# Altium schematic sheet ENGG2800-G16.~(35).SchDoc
size A3
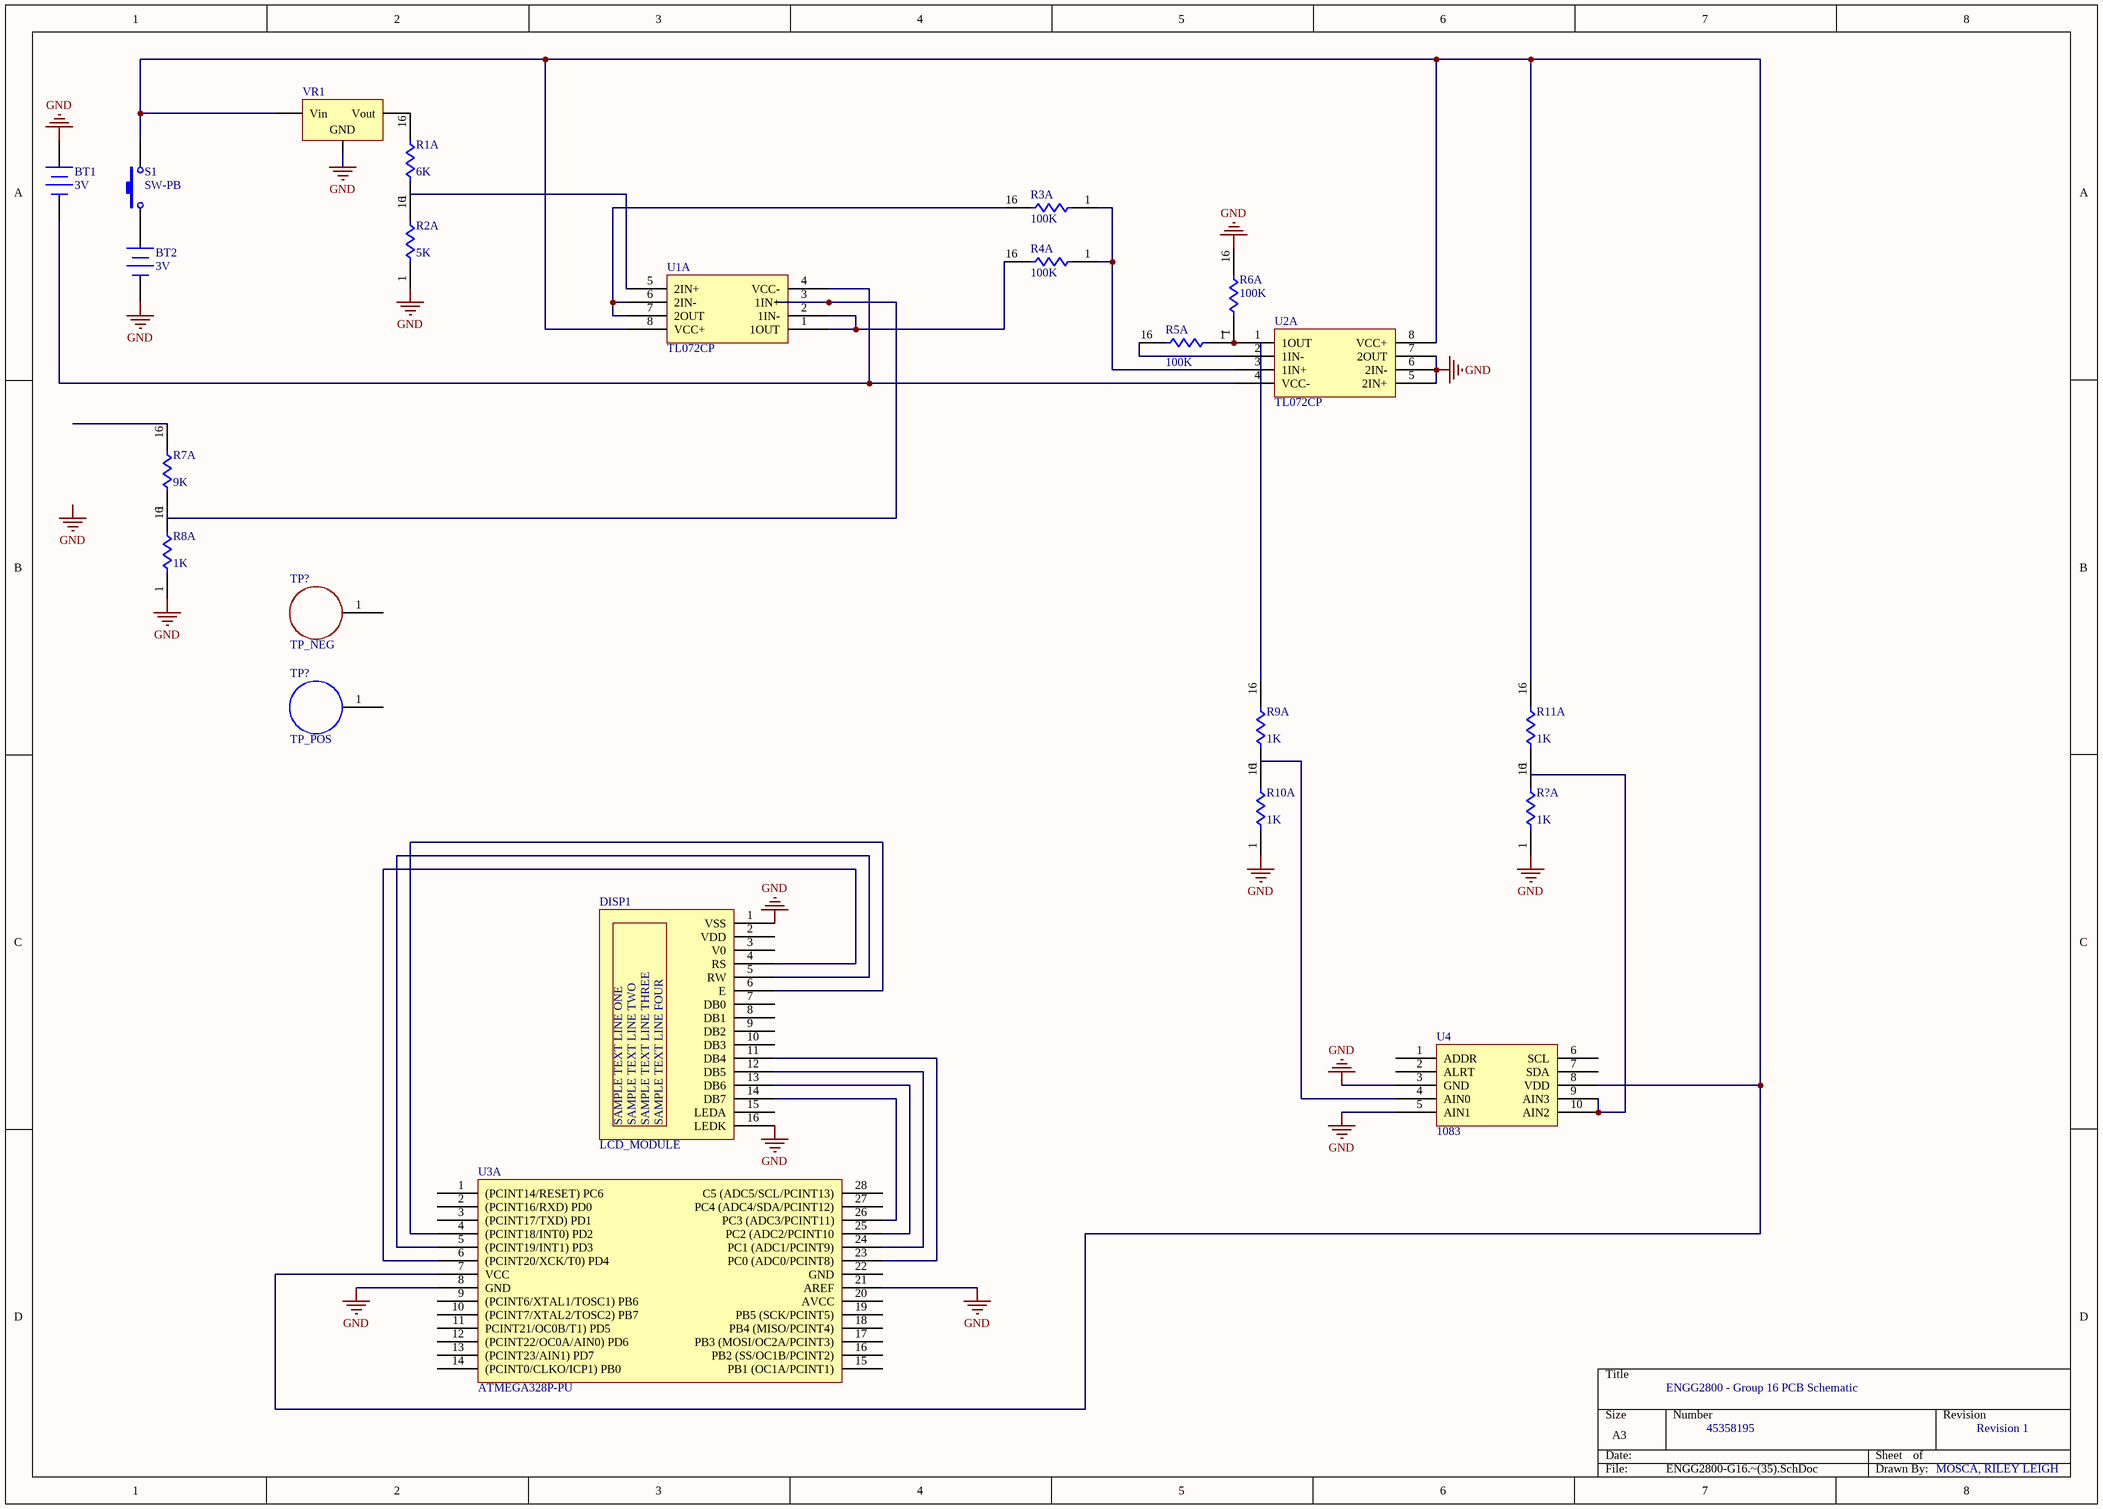
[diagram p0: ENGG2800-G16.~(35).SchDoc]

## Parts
(Parts that share a designator on the sheet are numbered #1, #2 ... from top to bottom, then left to right.)
BT1  3V  [BAT-2]
BT2  3V  [BAT-2]
DISP1  LCD_MODULE
R1  value 6K  [SOIC16_N]  (hidden comment: Res Pack1)  (part A of 8)
R2  value 5K  [SOIC16_N]  (hidden comment: Res Pack1)  (part A of 8)
R3  value 100K  [SOIC16_N]  (hidden comment: Res Pack1)  (part A of 8)
R4  value 100K  [SOIC16_N]  (hidden comment: Res Pack1)  (part A of 8)
R5  value 100K  [SOIC16_N]  (hidden comment: Res Pack1)  (part A of 8)
R6  value 100K  [SOIC16_N]  (hidden comment: Res Pack1)  (part A of 8)
R7  value 9K  [SOIC16_N]  (hidden comment: Res Pack1)  (part A of 8)
R8  value 1K  [SOIC16_N]  (hidden comment: Res Pack1)  (part A of 8)
R9  value 1K  [SOIC16_N]  (hidden comment: Res Pack1)  (part A of 8)
R10  value 1K  [SOIC16_N]  (hidden comment: Res Pack1)  (part A of 8)
R11  value 1K  [SOIC16_N]  (hidden comment: Res Pack1)  (part A of 8)
R?  value 1K  [SOIC16_N]  (hidden comment: Res Pack1)  (part A of 8)
S1  SW-PB  [SPST-2]
TP?#1  TP_NEG
TP?#2  TP_POS
U1  TL072CP  (part A of 4)
U2  TL072CP  (part A of 4)
U3  ATMEGA328P-PU  (part A of 2)
U4  1083
VR1  Volt Reg  [D2PAK_N]  (value not drawn)

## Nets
GND: BT1.1(+) BT2.2(-) DISP1.1(VSS) DISP1.16(LEDK) R2.1 R6.16 R8.1 R10.1 R?.1 U2.5(2IN+) U2.6(2IN-) U2.7(2OUT) U3.8(GND) U3.21(AREF) U4.3(GND) U4.5(AIN1) VR1.2(GND)
NetBT1_2: BT1.2(-) U1.4(VCC-) U2.4(VCC-)
NetDISP1_4: DISP1.4(RS) U3.6((PCINT20/XCK/T0)_PD4)
NetDISP1_5: DISP1.5(RW) U3.5((PCINT19/INT1)_PD3)
NetDISP1_6: DISP1.6(E) U3.4((PCINT18/INT0)_PD2)
NetDISP1_11: DISP1.11(DB4) U3.23(PC0_(ADC0/PCINT8))
NetDISP1_12: DISP1.12(DB5) U3.24(PC1_(ADC1/PCINT9))
NetDISP1_13: DISP1.13(DB6) U3.25(PC2_(ADC2/PCINT10)
NetDISP1_14: DISP1.14(DB7) U3.26(PC3_(ADC3/PCINT11))
NetR1_16: R1.16 VR1.3(Vout)
NetR2_16: R2.16 U1.5(2IN+)
NetR3_1: R3.1 R4.1 U2.3(1IN+)
NetR3_16: R3.16 U1.6(2IN-) U1.7(2OUT)
NetR4_16: R4.16 U1.1(1OUT) U1.2(1IN-)
NetR5_1: R5.1 R6.1 U2.1(1OUT)
NetR5_16: R5.16 U2.2(1IN-)
NetR7_1: R7.1 U1.3(1IN+)
NetR10_16: R10.16 U4.4(AIN0)
NetR11_1: R11.1 U4.9(AIN3) U4.10(AIN2)
NetR11_16: R11.16 S1.2 U1.8(VCC+) U2.8(VCC+) U3.7(VCC) U4.8(VDD) VR1.1(Vin)

Not connected (* = marked no-connect by the designer): BT2 1(+); DISP1 2(VDD) 3(V0) 7(DB0) 8(DB1) 9(DB2) 10(DB3) 15(LEDA); R1 1; R7 16; R8 16; R9 1 16; R? 16; S1 1; TP?#1 1(5); TP?#2 1(5); U3 1((PCINT14/RESET)_PC6) 2((PCINT16/RXD)_PD0) 3((PCINT17/TXD)_PD1) 9((PCINT6/XTAL1/TOSC1)_PB6) 10((PCINT7/XTAL2/TOSC2)_PB7) 11(PCINT21/OC0B/T1)_PD5) 12((PCINT22/OC0A/AIN0)_PD6) 13((PCINT23/AIN1)_PD7) 14((PCINT0/CLKO/ICP1)_PB0) 15(PB1_(OC1A/PCINT1)) 16(PB2_(SS/OC1B/PCINT2)) 17(PB3_(MOSI/OC2A/PCINT3)) 18(PB4_(MISO/PCINT4)) 19(PB5_(SCK/PCINT5)) 20(AVCC) 22(GND) 27(PC4_(ADC4/SDA/PCINT12)) 28(C5_(ADC5/SCL/PCINT13)); U4 1(ADDR) 2(ALRT) 6(SCL) 7(SDA)

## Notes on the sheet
- ENGG2800 - Group 16 PCB Schematic
- 45358195
- Revision 1
- MOSCA, RILEY LEIGH
- Labels drawn without touching a wire or pin: GND

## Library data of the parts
BT1 BT2 = Battery: Multicell Battery
R1-R11 R? = Res Pack1: Isolated Resistor Network - Parts; Sim Note: Enter the Resistance value into parameter field.
S1 = SW-PB: Switch
TP?#1 = TP_NEG: Test Point MultiPurpose THM .445 L .125OD Heat Resistant Nylon 46 Red; Manufacturer: Keystone Electronics; Manufacturer Part Number: 5010; Body Material: Bronze,PBT; Plating: Silver; Number of Ports: 1; Inside Diameter: 1.78mm; Hole Diameter: 1.6mm
TP?#2 = TP_POS: Test Point MultiPurpose THM .445 L .125OD Heat Resistant Nylon 46 Red; Manufacturer: Keystone Electronics; Manufacturer Part Number: 5010; Body Material: Bronze,PBT; Plating: Silver; Number of Ports: 1; Inside Diameter: 1.78mm; Hole Diameter: 1.6mm
U1 U2 = TL072CP: IC, OP AMP, DUAL JFET, DIP8; Bandwidth:3MHz; No. of Amplifiers:2; Slew Rate:13V/ s; Supply Voltage Range:7V to 36V; Amplifier Case Style:DIP; No. of Pins:8; Operating Temperature Min:0 C; Operating Temperature Max:70 C; ;RoHS Compliant: Yes; Manufacturer: Texas Instruments; Bandwidth: 3MHz; Number of Channels: 2; Voltage Gain: 106.02dB; Nominal Supply Current: 5mA; Max Supply Voltage: 18V; Min Dual Supply Voltage: 3.5V; Dual Supply Voltage: 9V; Common Mode Rejection Ratio: 70dB; Slew Rate: 13V/µs; Max I/O Voltage: 10mV; Input Bias Current: 200pA; Input Offset Voltage (Vos): 3mV; Operating Supply Current: 1.4mA
U3 = ATMEGA328P-PU: IC MCU 8BIT 32KB FLASH 28DIP; Manufacturer: Microchip / Atmel; Core Architecture: AVR; RAM Size: 2KB; Number of PWM Channels: 6; Number of Timers/Counters: 3; Min Supply Voltage: 1.8V; Max Supply Voltage: 5.5V; Interface: I2C,SPI,UART,USART,2-Wire; Number of I/Os: 23; Frequency: 20MHz; Oscillator Type: Internal; Data Bus Width: 8b; Number of SPI Channels: 1; Watchdog Timer: Yes; Peripherals: Brown-out Detect/Reset,POR,PWM,WDT
U4 = 1083: EVAL BOARD ADS1115 16-BIT ADC; Manufacturer: Adafruit Industries; Number of Bits: 12; Evaluation Kit: Yes; Number of A/D Converters: 1; Sampling Rate: 3300S/s; Interface: I2C,Serial
VR1 = Volt Reg: Voltage Regulator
